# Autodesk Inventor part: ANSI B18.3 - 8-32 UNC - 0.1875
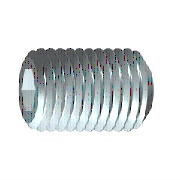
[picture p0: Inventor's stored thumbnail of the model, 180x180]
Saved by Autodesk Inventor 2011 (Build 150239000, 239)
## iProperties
IsCustomPart: 0
Created: 2010-02
Part Number: ANSI B18.3 - 8-32 UNC - 0.1875
Material: Steel, Mild
Description: Type B - Hexagon Socket Set Screw - Cup Point
Document SubType Name: Modeling
Standard: ANSI B18.3
Designer: Phil
Standard Revision: 2003
Standards Organization: ANSI
Language: en-US
Size Designation: 8-32 UNC - 0.1875
Categories: <MemberInstance><Categories><Category DisplayName="Fasteners" InternalName="e4da775c-781d-43d5-af7c-5136215cf5a6" Mnemonic="FSTN"><Category DisplayName="Bolts"
Density: 1 g/cm^3
Author: Phil
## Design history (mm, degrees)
revolve "Body" stored, may be unused: angle "d6" = 90 deg
sketch "Sketch2"
  geometry: L1 (1.144, 0)-(0.572, -0.991); L2 (0.572, -0.991)-(-0.572, -0.991); L3 (-0.572, -0.991)-(-1.144, 0); L4 (-1.144, 0)-(-0.572, 0.991); L5 (-0.572, 0.991)-(0.572, 0.991); L6 (0.572, 0.991)-(1.144, 0); C1 r 2.083 at (0, 0) reference; A1 r 1.144 centre (0, 0) between (1.144, 0) and (0.572, -0.991) reference; 1 further point
  constraints: 12 end point, 2 point on circle, 1 coincident, 1 horizontal, 11 other
extrude "Slot" join sketch "Sketch2" distance "d8" = 2.032 (= INTI); taper "d9" = 0 deg
workaxis "Work Axis1"
workplane "Work Plane1"
body "Solid1"
chamfer "Chamfer1" distance "d10" = 1.0414 (= -0.5 x SPD + 0.5 x NND); stored, may be unused: angle "d11" = 45 deg (= FAWI), second distance "d33" = 1.0414 (= -0.5 x SPD + 0.5 x NND)
feature "Thread" dims "d14" = 4.7625 (= NLG), "d15" = 0
chamfer "Chamfer2" distance "d12" = 0.42926 (= -0.5 x GD1 + 0.5 x NND); stored, may be unused: angle "d13" = 45 deg (= FAWI), second distance "d34" = 0.42926 (= -0.5 x GD1 + 0.5 x NND)
sketch "Sketch1"
  geometry: L1 (0.626, 0)-(2.07, 0); L2 (4.763, 1.144)-(4.763, 2.083); L3 (4.763, 2.083)-(0, 2.083); L4 (4.763, 1.144)-(2.731, 1.144); L5 (2.731, 1.144)-(2.07, 0); L6 (0, 1.041)-(0.626, 0); L7 (0, -0.417)-(0, 2.499) reference; L8 (0, 1.041)-(0, 2.083); 1 further point
  constraints: 14 end point, 2 parallel, 2 perpendicular, 1 horizontal, 1 midpoint, 1 point on line
  dimensions: "d0" = 2.032 distance of L2.start L4.end (= INTI); "d1" = 60 deg angle of L5 L1; "d2" = 4.1656 diameter of L3 L1 (= NND); "d3" = 2.28769 diameter of L4 L1 (= 1.1547 x SW); "d4" = 4.7625 distance from line of L2 L6.start (= NLG); "d5" = 59 deg angle of L1 L6 (= 0.5 x ANG); "d7" = 2.0828 diameter of L6.start L1 (= SPD)
other parameters: "NND" = 4.1656 [user parameter; used in 5 equation terms], "NLG" = 4.7625 [user parameter; used in 2 equation terms], "INTI" = 2.032 [user parameter; used in 2 equation terms], "FAWI" = 45 deg [user parameter; used in 3 equation terms], "SW" = 1.9812 [user parameter; used in 2 equation terms], "GD1" = 3.30708 [user parameter; used in 2 equation terms], "ANG" = 118 deg [user parameter; used in 1 equation term], "FAWI1" = 45 deg (= FAWI) [user parameter], "SPD" = 2.0828 [user parameter; used in 3 equation terms], "d16" = 0, "d35" = 0, "d37" = 0, "TOA" = 30 deg [user parameter], "THREADDIA" = 4.1656 [user parameter], "PTC" = 0.79375 (computed from TPU) [user parameter], "E0" = 2.28829 (= 1.155 x SW) [user parameter]
